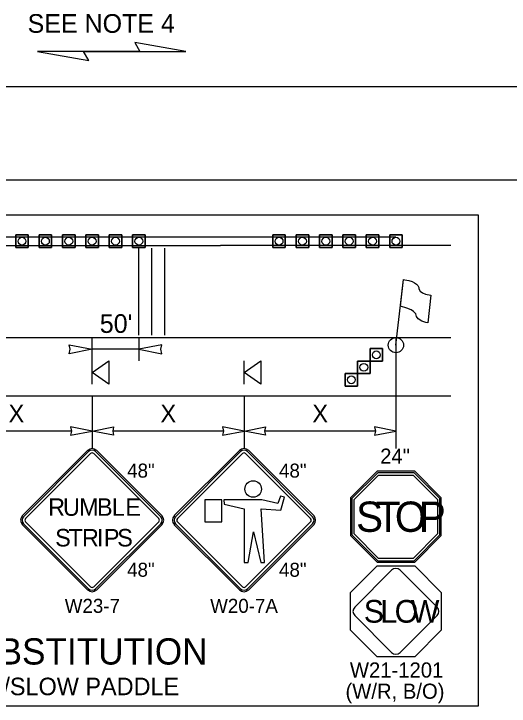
# Model space of a CAD drawing. Extents: x 99999.1 to 100095.7, y 99995 to 100010.7.
# Drawn here: x 100047.123 to 100049.243, y 100003.48 to 100006.443 of the extents above; entities that cross this region are included whole.
import ezdxf

# ---------------------------------------------------------------- set-up
doc = ezdxf.new("R2010")
doc.units = 0
for name, color, linetype in [('RD_ED_ShoulderPavedEdge', 7, 'Continuous'), ('RD_MK_LineDblYellowCenter', 7, 'Continuous'), ('RD_MK_LineEdgeWhite', 7, 'Continuous'), ('RD_MK_LineNoPass', 7, 'Continuous'), ('RD_MK_LineSkipCenter', 7, 'Continuous'), ('SH_DE_DetailHeading2Text', 7, 'Continuous'), ('TR_SN_ConstructionSigns', 7, 'Continuous'), ('TR_WZ_FlaggingStation', 7, 'Continuous'), ('TR_WZ_PortableSignMountBlk-Org', 7, 'Continuous'), ('TR_WZ_TrafficCone', 7, 'Continuous'), ('TR_WZ_WorkZoneDetails', 7, 'Continuous'), ('TR_WZ_WorkZoneTextCurrent', 7, 'Continuous')]:
    doc.layers.add(name, color=color, linetype=linetype)

msp = doc.modelspace()

# ---------------------------------------------------------------- linework, layer by layer
at = {"layer": 'RD_ED_ShoulderPavedEdge'}
for p, q in [((100040.1076, 100005.7323), (100055.6424, 100005.7323)), ((100045.2015, 100004.8073), (100048.9925, 100004.8073))]:
    msp.add_line(p, q, dxfattribs=at)
at = {"layer": 'RD_MK_LineDblYellowCenter'}
for p, q in [((100045.2015, 100005.4886), (100048.0081, 100005.4886)), ((100045.2015, 100005.4511), (100048.0081, 100005.4511))]:
    msp.add_line(p, q, dxfattribs=at)
at = {"layer": 'RD_MK_LineEdgeWhite'}
for p, q in [((100040.1076, 100006.1323), (100055.6424, 100006.1323)), ((100045.2015, 100005.0573), (100048.9925, 100005.0573))]:
    msp.add_line(p, q, dxfattribs=at)
at = {"layer": 'RD_MK_LineNoPass'}
msp.add_line((100048.0081, 100005.4886), (100048.7581, 100005.4886), dxfattribs=at)
at = {"layer": 'RD_MK_LineSkipCenter'}
msp.add_lwpolyline([(100048.9925, 100005.4511), (100048.0081, 100005.4511)], dxfattribs=at)
at = {"layer": 'TR_SN_ConstructionSigns'}
for p, q in [((100047.4382, 100004.5741), (100047.1598, 100004.2957)), ((100047.4432, 100004.5691), (100047.1647, 100004.2907)), ((100047.173, 100004.2824), (100047.4515, 100004.5608)), ((100047.4647, 100004.5608), (100047.7431, 100004.2824)), ((100047.7514, 100004.2907), (100047.473, 100004.5691)), ((100047.7564, 100004.2957), (100047.478, 100004.5741)), ((100048.0882, 100004.5741), (100047.8098, 100004.2957)), ((100048.0932, 100004.5691), (100047.8147, 100004.2907)), ((100047.823, 100004.2824), (100048.1015, 100004.5608)), ((100048.1147, 100004.5608), (100048.3931, 100004.2824)), ((100048.4014, 100004.2907), (100048.123, 100004.5691)), ((100048.4064, 100004.2957), (100048.128, 100004.5741)), ((100048.6775, 100004.4851), (100048.5636, 100004.3713)), ((100048.68, 100004.4791), (100048.5697, 100004.3687)), ((100048.5798, 100004.3646), (100048.6842, 100004.4689)), ((100048.8385, 100004.4851), (100048.6775, 100004.4851)), ((100048.836, 100004.4791), (100048.68, 100004.4791)), ((100048.6842, 100004.4689), (100048.8318, 100004.4689)), ((100048.8318, 100004.4689), (100048.9362, 100004.3646)), ((100048.9463, 100004.3687), (100048.836, 100004.4791)), ((100048.9524, 100004.3713), (100048.8385, 100004.4851)), ((100048.5636, 100004.3713), (100048.5636, 100004.2102)), ((100048.5697, 100004.3687), (100048.5697, 100004.2127)), ((100048.9463, 100004.2127), (100048.9463, 100004.3687)), ((100048.9524, 100004.2102), (100048.9524, 100004.3713)), ((100048.5798, 100004.2169), (100048.5798, 100004.3646)), ((100048.9362, 100004.3646), (100048.9362, 100004.2169)), ((100047.1598, 100004.2559), (100047.4382, 100003.9775)), ((100047.1647, 100004.2609), (100047.4432, 100003.9824)), ((100047.4515, 100003.9907), (100047.173, 100004.2692)), ((100047.7431, 100004.2692), (100047.4647, 100003.9907)), ((100047.473, 100003.9824), (100047.7514, 100004.2609)), ((100047.478, 100003.9775), (100047.7564, 100004.2559)), ((100047.8098, 100004.2559), (100048.0882, 100003.9775)), ((100047.8147, 100004.2609), (100048.0932, 100003.9824)), ((100048.1015, 100003.9907), (100047.823, 100004.2692)), ((100048.3931, 100004.2692), (100048.1147, 100003.9907)), ((100048.123, 100003.9824), (100048.4014, 100004.2609)), ((100048.128, 100003.9775), (100048.4064, 100004.2559)), ((100048.5636, 100004.2102), (100048.6775, 100004.0963)), ((100048.5697, 100004.2127), (100048.68, 100004.1024)), ((100048.6842, 100004.1125), (100048.5798, 100004.2169)), ((100048.9362, 100004.2169), (100048.8318, 100004.1125)), ((100048.836, 100004.1024), (100048.9463, 100004.2127)), ((100048.8385, 100004.0963), (100048.9524, 100004.2102)), ((100048.68, 100004.1024), (100048.836, 100004.1024)), ((100048.8318, 100004.1125), (100048.6842, 100004.1125)), ((100048.6775, 100004.0963), (100048.8385, 100004.0963)), ((100048.7397, 100004.0618), (100048.5819, 100003.9041)), ((100048.9341, 100003.9041), (100048.7763, 100004.0618)), ((100048.5819, 100003.8674), (100048.7397, 100003.7097)), ((100048.7763, 100003.7097), (100048.9341, 100003.8674))]:
    msp.add_line(p, q, dxfattribs=at)
for points in [[(100048.022, 100004.3628), (100048.023, 100004.3447), (100048.1085, 100004.3248), (100048.1085, 100004.0945), (100048.1252, 100004.0945), (100048.1487, 100004.2254), (100048.1799, 100004.0945), (100048.1957, 100004.0945), (100048.1819, 100004.3247), (100048.2654, 100004.318), (100048.2812, 100004.3738), (100048.264, 100004.3787), (100048.2529, 100004.3468), (100048.1839, 100004.3628)], [(100047.9404, 100004.3626), (100047.9404, 100004.269), (100048.0134, 100004.269), (100048.0134, 100004.3626)], [(100048.9524, 100003.9663), (100048.9524, 100003.8052), (100048.8385, 100003.6913), (100048.6775, 100003.6913), (100048.5636, 100003.8052), (100048.5636, 100003.9663), (100048.6775, 100004.0801), (100048.8385, 100004.0801)]]:
    msp.add_lwpolyline(points, close=True, dxfattribs=at)
msp.add_circle((100048.1472, 100004.4091), 0.0354, dxfattribs=at)
for centre, radius, start, end in [((100047.4581, 100004.5542), 0.0281, 45, 135), ((100047.4581, 100004.5542), 0.0211, 45, 135), ((100048.1081, 100004.5542), 0.0281, 45, 135), ((100048.1081, 100004.5542), 0.0211, 45, 135), ((100047.4581, 100004.5542), 0.00938, 45, 135), ((100048.1081, 100004.5542), 0.00938, 45, 135), ((100047.1797, 100004.2758), 0.0281, 135, 225), ((100047.1797, 100004.2758), 0.0211, 135, 225), ((100047.1797, 100004.2758), 0.00938, 135, 225), ((100047.7365, 100004.2758), 0.00938, 315, 45), ((100047.7365, 100004.2758), 0.0211, 315, 45), ((100047.7365, 100004.2758), 0.0281, 315, 45), ((100047.8297, 100004.2758), 0.0281, 135, 225), ((100047.8297, 100004.2758), 0.0211, 135, 225), ((100047.8297, 100004.2758), 0.00938, 135, 225), ((100048.3865, 100004.2758), 0.00938, 315, 45), ((100048.3865, 100004.2758), 0.0211, 315, 45), ((100048.3865, 100004.2758), 0.0281, 315, 45), ((100048.758, 100004.0435), 0.0259, 45, 135), ((100047.4581, 100003.9974), 0.00938, 225, 315), ((100048.1081, 100003.9974), 0.00938, 225, 315), ((100047.4581, 100003.9974), 0.0281, 225, 315), ((100047.4581, 100003.9974), 0.0211, 225, 315), ((100048.1081, 100003.9974), 0.0281, 225, 315), ((100048.1081, 100003.9974), 0.0211, 225, 315), ((100048.6003, 100003.8857), 0.0259, 135, 225), ((100048.9157, 100003.8857), 0.0259, 315, 45), ((100048.758, 100003.728), 0.0259, 225, 315)]:
    msp.add_arc(centre, radius, start, end, dxfattribs=at)
at = {"layer": 'TR_WZ_FlaggingStation'}
for p, q in [((100048.7581, 100005.0248), (100048.7901, 100005.3058)), ((100048.7771, 100005.1917), (100048.7902, 100005.3061)), ((100048.9081, 100005.2383), (100048.8948, 100005.1211)), ((100048.7771, 100005.1917), (100048.7771, 100005.1917))]:
    msp.add_line(p, q, dxfattribs=at)
for points in [[(100048.7902, 100005.3061), (100048.7959, 100005.3048), (100048.8137, 100005.3014), (100048.8276, 100005.2972), (100048.8372, 100005.2911), (100048.8458, 100005.2864), (100048.8515, 100005.2796), (100048.8557, 100005.2717), (100048.8562, 100005.2655), (100048.8616, 100005.2563), (100048.8724, 100005.2489), (100048.8848, 100005.2437), (100048.9081, 100005.2383)], [(100048.8948, 100005.1211), (100048.8867, 100005.1225), (100048.869, 100005.1271), (100048.8533, 100005.1376), (100048.8468, 100005.1482), (100048.8429, 100005.1585), (100048.8338, 100005.1694), (100048.8229, 100005.1756), (100048.8055, 100005.1827), (100048.7771, 100005.1917)]]:
    msp.add_lwpolyline(points, dxfattribs=at)
msp.add_circle((100048.7581, 100005.0248), 0.0325, dxfattribs=at)
at = {"layer": 'TR_WZ_PortableSignMountBlk-Org'}
for p, q in [((100047.4581, 100004.8574), (100047.4581, 100004.9574)), ((100048.1081, 100004.8574), (100048.1081, 100004.9574))]:
    msp.add_line(p, q, dxfattribs=at)
for points in [[(100047.4581, 100004.9073), (100047.5299, 100004.9574), (100047.5299, 100004.8574)], [(100048.1081, 100004.9073), (100048.1799, 100004.9574), (100048.1799, 100004.8574)]]:
    msp.add_lwpolyline(points, close=True, dxfattribs=at)
at = {"layer": 'TR_WZ_TrafficCone'}
for points in [[(100047.1848, 100005.4965), (100047.1314, 100005.4965), (100047.1314, 100005.4432), (100047.1848, 100005.4432), (100047.1848, 100005.4965)], [(100047.1848, 100005.4432), (100047.1314, 100005.4432), (100047.1314, 100005.4965), (100047.1848, 100005.4965), (100047.1848, 100005.4432)], [(100047.2848, 100005.4965), (100047.2314, 100005.4965), (100047.2314, 100005.4432), (100047.2848, 100005.4432), (100047.2848, 100005.4965)], [(100047.2848, 100005.4432), (100047.2314, 100005.4432), (100047.2314, 100005.4965), (100047.2848, 100005.4965), (100047.2848, 100005.4432)], [(100047.3848, 100005.4965), (100047.3314, 100005.4965), (100047.3314, 100005.4432), (100047.3848, 100005.4432), (100047.3848, 100005.4965)], [(100047.3848, 100005.4432), (100047.3314, 100005.4432), (100047.3314, 100005.4965), (100047.3848, 100005.4965), (100047.3848, 100005.4432)], [(100047.4848, 100005.4965), (100047.4314, 100005.4965), (100047.4314, 100005.4432), (100047.4848, 100005.4432), (100047.4848, 100005.4965)], [(100047.4848, 100005.4432), (100047.4314, 100005.4432), (100047.4314, 100005.4965), (100047.4848, 100005.4965), (100047.4848, 100005.4432)], [(100047.5848, 100005.4965), (100047.5314, 100005.4965), (100047.5314, 100005.4432), (100047.5848, 100005.4432), (100047.5848, 100005.4965)], [(100047.5848, 100005.4432), (100047.5314, 100005.4432), (100047.5314, 100005.4965), (100047.5848, 100005.4965), (100047.5848, 100005.4432)], [(100047.6848, 100005.4965), (100047.6314, 100005.4965), (100047.6314, 100005.4432), (100047.6848, 100005.4432), (100047.6848, 100005.4965)], [(100047.6848, 100005.4432), (100047.6314, 100005.4432), (100047.6314, 100005.4965), (100047.6848, 100005.4965), (100047.6848, 100005.4432)], [(100048.2848, 100005.4965), (100048.2314, 100005.4965), (100048.2314, 100005.4432), (100048.2848, 100005.4432), (100048.2848, 100005.4965)], [(100048.2848, 100005.4432), (100048.2314, 100005.4432), (100048.2314, 100005.4965), (100048.2848, 100005.4965), (100048.2848, 100005.4432)], [(100048.3848, 100005.4965), (100048.3314, 100005.4965), (100048.3314, 100005.4432), (100048.3848, 100005.4432), (100048.3848, 100005.4965)], [(100048.3848, 100005.4432), (100048.3314, 100005.4432), (100048.3314, 100005.4965), (100048.3848, 100005.4965), (100048.3848, 100005.4432)], [(100048.4848, 100005.4965), (100048.4314, 100005.4965), (100048.4314, 100005.4432), (100048.4848, 100005.4432), (100048.4848, 100005.4965)], [(100048.4848, 100005.4432), (100048.4314, 100005.4432), (100048.4314, 100005.4965), (100048.4848, 100005.4965), (100048.4848, 100005.4432)], [(100048.5848, 100005.4965), (100048.5314, 100005.4965), (100048.5314, 100005.4432), (100048.5848, 100005.4432), (100048.5848, 100005.4965)], [(100048.5848, 100005.4432), (100048.5314, 100005.4432), (100048.5314, 100005.4965), (100048.5848, 100005.4965), (100048.5848, 100005.4432)], [(100048.6848, 100005.4965), (100048.6314, 100005.4965), (100048.6314, 100005.4432), (100048.6848, 100005.4432), (100048.6848, 100005.4965)], [(100048.6848, 100005.4432), (100048.6314, 100005.4432), (100048.6314, 100005.4965), (100048.6848, 100005.4965), (100048.6848, 100005.4432)], [(100048.7848, 100005.4965), (100048.7314, 100005.4965), (100048.7314, 100005.4432), (100048.7848, 100005.4432), (100048.7848, 100005.4965)], [(100048.7848, 100005.4432), (100048.7314, 100005.4432), (100048.7314, 100005.4965), (100048.7848, 100005.4965), (100048.7848, 100005.4432)], [(100048.6474, 100005.01), (100048.7008, 100005.01), (100048.7008, 100004.9567), (100048.6474, 100004.9567), (100048.6474, 100005.01)], [(100048.6474, 100004.9567), (100048.7008, 100004.9567), (100048.7008, 100005.01), (100048.6474, 100005.01), (100048.6474, 100004.9567)], [(100048.5941, 100004.9567), (100048.6474, 100004.9567), (100048.6474, 100004.9033), (100048.5941, 100004.9033), (100048.5941, 100004.9567)], [(100048.5941, 100004.9033), (100048.6474, 100004.9033), (100048.6474, 100004.9567), (100048.5941, 100004.9567), (100048.5941, 100004.9033)], [(100048.5408, 100004.9033), (100048.5941, 100004.9033), (100048.5941, 100004.85), (100048.5408, 100004.85), (100048.5408, 100004.9033)], [(100048.5408, 100004.85), (100048.5941, 100004.85), (100048.5941, 100004.9033), (100048.5408, 100004.9033), (100048.5408, 100004.85)]]:
    msp.add_lwpolyline(points, dxfattribs=at)
for centre in [(100047.1581, 100005.4698), (100047.2581, 100005.4698), (100047.3581, 100005.4698), (100047.4581, 100005.4698), (100047.5581, 100005.4698), (100047.6581, 100005.4698), (100048.2581, 100005.4698), (100048.3581, 100005.4698), (100048.4581, 100005.4698), (100048.5581, 100005.4698), (100048.6581, 100005.4698), (100048.7581, 100005.4698), (100048.6741, 100004.9833), (100048.6208, 100004.93), (100048.5674, 100004.8767)]:
    msp.add_circle(centre, 0.0167, dxfattribs=at)
at = {"layer": 'TR_WZ_WorkZoneDetails'}
for p, q in [((100047.4213, 100006.2816), (100047.6624, 100006.2816)), ((100047.6624, 100006.2816), (100047.4213, 100006.2816)), ((100047.6581, 100005.0673), (100047.6581, 100005.4398)), ((100047.7137, 100005.0673), (100047.7137, 100005.4398)), ((100047.7686, 100005.0673), (100047.7686, 100005.4398)), ((100047.4581, 100004.9574), (100047.4581, 100005.0573)), ((100047.6581, 100005.0573), (100047.6581, 100004.9574)), ((100048.7581, 100005.0573), (100048.7581, 100004.5823)), ((100047.6581, 100005.0074), (100047.4581, 100005.0074)), ((100047.4581, 100004.8073), (100047.4581, 100004.5823)), ((100048.1081, 100004.8073), (100048.1081, 100004.5823)), ((100047.3702, 100004.6573), (100046.896, 100004.6573)), ((100048.0202, 100004.6573), (100047.546, 100004.6573)), ((100048.6702, 100004.6573), (100048.196, 100004.6573))]:
    msp.add_line(p, q, dxfattribs=at)
for points in [[(100047.859, 100006.2816), (100047.6401, 100006.3202), (100047.6624, 100006.2816)], [(100047.2248, 100006.2816), (100047.4436, 100006.243), (100047.4213, 100006.2816)], [(100047.4581, 100005.0074), (100047.3598, 100004.9881), (100047.3644, 100005.0074), (100047.3598, 100005.0267)], [(100047.6581, 100005.0074), (100047.7564, 100004.9881), (100047.7518, 100005.0074), (100047.7564, 100005.0267)], [(100047.4581, 100004.6573), (100047.3659, 100004.6754), (100047.3702, 100004.6573), (100047.3659, 100004.6393)], [(100047.4581, 100004.6573), (100047.5502, 100004.6754), (100047.546, 100004.6573), (100047.5502, 100004.6393)], [(100048.1081, 100004.6573), (100048.0159, 100004.6754), (100048.0202, 100004.6573), (100048.0159, 100004.6393)], [(100048.1081, 100004.6573), (100048.2002, 100004.6754), (100048.196, 100004.6573), (100048.2002, 100004.6393)], [(100048.7581, 100004.6573), (100048.6659, 100004.6754), (100048.6702, 100004.6573), (100048.6659, 100004.6393)]]:
    msp.add_lwpolyline(points, close=True, dxfattribs=at)
at = {"layer": 'TR_WZ_WorkZoneTextCurrent'}
msp.add_lwpolyline([(100045.1015, 100005.5823), (100049.1102, 100005.5823), (100049.1102, 100003.4799), (100045.1015, 100003.4799)], close=True, dxfattribs=at)

# ---------------------------------------------------------------- texts
at = {"layer": 'SH_DE_DetailHeading2Text'}
msp.add_text('HUMAN FLAGGER SUBSTITUTION', height=0.1125, rotation=360, dxfattribs=at).set_placement((100045.4946, 100003.658))
at = {"layer": 'TR_SN_ConstructionSigns'}
for s, height, p in [('24"', 0.0648, (100048.6908, 100004.5175)), ('R', 0.075, (100047.2695, 100004.2945)), ('U', 0.075, (100047.3332, 100004.2945)), ('M', 0.075, (100047.4022, 100004.2945)), ('B', 0.075, (100047.4787, 100004.2945)), ('L', 0.075, (100047.5425, 100004.2945)), ('E', 0.075, (100047.6002, 100004.2945)), ('S', 0.1296, (100048.5876, 100004.2259)), ('T', 0.1296, (100048.6718, 100004.2259)), ('O', 0.1296, (100048.7535, 100004.2259)), ('P', 0.1296, (100048.8559, 100004.2259)), ('S', 0.075, (100047.2998, 100004.1633)), ('T', 0.075, (100047.3568, 100004.1633)), ('R', 0.075, (100047.4146, 100004.1633)), ('I', 0.075, (100047.4783, 100004.1633)), ('P', 0.075, (100047.5083, 100004.1633)), ('S', 0.075, (100047.5653, 100004.1633)), ('S', 0.0972, (100048.6205, 100003.8371)), ('L', 0.0972, (100048.6914, 100003.8371)), ('O', 0.0972, (100048.7527, 100003.8371)), ('W', 0.0972, (100048.8217, 100003.8371))]:
    msp.add_text(s, height=height, dxfattribs=at).set_placement(p)
for s, height, p in [('48"', 0.06, (100047.6079, 100004.4579)), ('48"', 0.06, (100048.2579, 100004.4579)), ('48"', 0.06, (100047.6079, 100004.0337)), ('48"', 0.06, (100048.2579, 100004.0337)), ('W23-7', 0.06, (100047.3409, 100003.8792)), ('W20-7A', 0.06, (100047.9632, 100003.8792)), ('W21-1201', 0.0648, (100048.5611, 100003.6022)), ('(W/R, B/O)', 0.0648, (100048.5423, 100003.5115))]:
    msp.add_text(s, height=height, rotation=360, dxfattribs=at).set_placement(p)
at = {"layer": 'TR_WZ_WorkZoneTextCurrent'}
for s, height, p in [('SEE NOTE 4', 0.08, (100047.1819, 100006.3616)), ("50'", 0.08, (100047.4908, 100005.0773)), ('UPDATE SIGNAGE & USE STOP/SLOW PADDLE', 0.075, (100045.5568, 100003.5268))]:
    msp.add_text(s, height=height, dxfattribs=at).set_placement(p)
for p in [(100047.1005, 100004.6948), (100047.7505, 100004.6948), (100048.4005, 100004.6948)]:
    msp.add_text('X', height=0.075, rotation=360, dxfattribs=at).set_placement(p)

doc.saveas('drawing.dxf')
